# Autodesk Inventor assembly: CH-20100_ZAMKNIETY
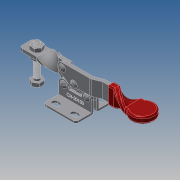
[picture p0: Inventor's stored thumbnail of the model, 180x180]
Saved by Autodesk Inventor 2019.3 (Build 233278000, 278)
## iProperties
Company: Î¢ÈíÖÐ¹ú
Created: 2012-09
Part Number: CH-20100_ZAMKNIETY
Material: Ogólny
Description: STEP AP203
Document SubType Name: Assembly
Designer: CADENGINEERING4
Sending System: SolidWorks 2010
Preprocessor: SwSTEP 2.0
Title: CH-20100.STEP
Author: Î¢ÈíÓÃ»§
Revision Number: ÈÎºÎ
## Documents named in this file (10)
- E:\STRONA\Horizontal toggle clamp\CH-20100\CH-20100_ZAMKNIETY.iam
- E:\STRONA\Horizontal toggle clamp\CH-20100\CH-20100-03 HANDLE.ipt
- E:\STRONA\Horizontal toggle clamp\CH-20100\CH-20100-08.ipt
- E:\STRONA\Horizontal toggle clamp\CH-20100\CH-20100-06.ipt
- E:\STRONA\Horizontal toggle clamp\CH-20100\CH-SA-042507 SPINDLE SUPPLIED.ipt
- E:\STRONA\Horizontal toggle clamp\CH-20100\CH-20100-02 SOLID BAR.ipt
- E:\STRONA\Horizontal toggle clamp\CH-20100\CH-20100-05.ipt
- E:\STRONA\Horizontal toggle clamp\CH-20100\M4 Nut.ipt
- E:\STRONA\Horizontal toggle clamp\CH-20100\CH-20100-01 FLANGED BASE.ipt
- E:\STRONA\Horizontal toggle clamp\CH-20100\CH-20100-04 CONNECTING-PLATE.ipt
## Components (12 placed, 12 different names)
1. CH-20100-03 HANDLE_1 — Zestawiające:1, Zestawiające:2, Zestawiające:3, Zestawiające:23, Zestawiające:24, Zestawiające:25, Zestawiające:26, Zestawiające:27, Przejściowe:1
2. CH-20100-08_2 — Zestawiające:22, Zestawiające:27
3. CH-20100-06_3 — Zestawiające:11, Zestawiające:12
4. CH-SA-042507 SPINDLE SUPPLIED_4 — Równoległe:1, Zestawiające:4, Zestawiające:5, Zestawiające:8
5. CH-20100-02 SOLID BAR_5 — Zestawiające:6, Zestawiające:7, Zestawiające:8, Zestawiające:15, Zestawiające:16, Zestawiające:22, Zestawiające:23, Zestawiające:24
6. CH-20100-05_6 — Zestawiające:1, Zestawiające:2, Zestawiające:3
7. M4 Nut_7 — Równoległe:1, Zestawiające:4, Zestawiające:7
8. CH-20100-01 FLANGED BASE_8 — Zestawiające:9, Zestawiające:10, Zestawiające:11, Zestawiające:12, Zestawiające:15, Zestawiające:16, Zestawiające:17, Zestawiające:18, Przejściowe:1
9. M4 Nut_9 — Zestawiające:5, Zestawiające:6
10. CH-20100-08_10 — Zestawiające:19, Zestawiające:26
11. CH-20100-06_11 — Zestawiające:17, Zestawiające:18
12. CH-20100-04 CONNECTING-PLATE_12 — Zestawiające:9, Zestawiające:10, Zestawiające:19, Zestawiające:25
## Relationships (25: Mate 23, Flush 1, Transitional 1)
- Zestawiające:1 [Mate]: CH-20100-03 HANDLE_1 ↔ CH-20100-05_6
- Zestawiające:2 [Mate]: CH-20100-03 HANDLE_1 ↔ CH-20100-05_6
- Zestawiające:3 [Mate]: CH-20100-03 HANDLE_1 ↔ CH-20100-05_6
- Równoległe:1 [Flush]: CH-SA-042507 SPINDLE SUPPLIED_4 ↔ M4 Nut_7
- Zestawiające:4 [Mate]: CH-SA-042507 SPINDLE SUPPLIED_4 ↔ M4 Nut_7
- Zestawiające:5 [Mate]: CH-SA-042507 SPINDLE SUPPLIED_4 ↔ M4 Nut_9
- Zestawiające:6 [Mate]: CH-20100-02 SOLID BAR_5 ↔ M4 Nut_9
- Zestawiające:7 [Mate]: CH-20100-02 SOLID BAR_5 ↔ M4 Nut_7
- Zestawiające:8 [Mate]: CH-SA-042507 SPINDLE SUPPLIED_4 ↔ CH-20100-02 SOLID BAR_5
- Zestawiające:9 [Mate]: CH-20100-01 FLANGED BASE_8 ↔ CH-20100-04 CONNECTING-PLATE_12
- Zestawiające:10 [Mate]: CH-20100-01 FLANGED BASE_8 ↔ CH-20100-04 CONNECTING-PLATE_12
- Zestawiające:11 [Mate]: CH-20100-06_3 ↔ CH-20100-01 FLANGED BASE_8
- Zestawiające:12 [Mate]: CH-20100-06_3 ↔ CH-20100-01 FLANGED BASE_8
- Zestawiające:15 [Mate]: CH-20100-02 SOLID BAR_5 ↔ CH-20100-01 FLANGED BASE_8
- Zestawiające:16 [Mate]: CH-20100-02 SOLID BAR_5 ↔ CH-20100-01 FLANGED BASE_8
- Zestawiające:17 [Mate]: CH-20100-01 FLANGED BASE_8 ↔ CH-20100-06_11
- Zestawiające:18 [Mate]: CH-20100-01 FLANGED BASE_8 ↔ CH-20100-06_11
- Zestawiające:19 [Mate]: CH-20100-08_10 ↔ CH-20100-04 CONNECTING-PLATE_12
- Zestawiające:22 [Mate]: CH-20100-08_2 ↔ CH-20100-02 SOLID BAR_5
- Zestawiające:23 [Mate]: CH-20100-03 HANDLE_1 ↔ CH-20100-02 SOLID BAR_5
- Zestawiające:24 [Mate]: CH-20100-03 HANDLE_1 ↔ CH-20100-02 SOLID BAR_5
- Zestawiające:25 [Mate]: CH-20100-03 HANDLE_1 ↔ CH-20100-04 CONNECTING-PLATE_12
- Zestawiające:26 [Mate]: CH-20100-03 HANDLE_1 ↔ CH-20100-08_10
- Zestawiające:27 [Mate]: CH-20100-03 HANDLE_1 ↔ CH-20100-08_2
- Przejściowe:1 [Transitional]: CH-20100-03 HANDLE_1 ↔ CH-20100-01 FLANGED BASE_8
